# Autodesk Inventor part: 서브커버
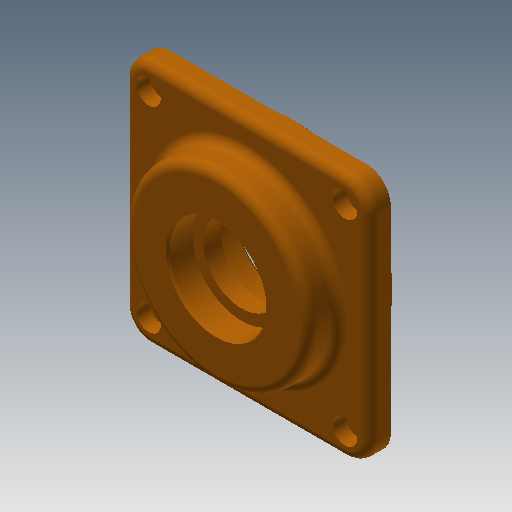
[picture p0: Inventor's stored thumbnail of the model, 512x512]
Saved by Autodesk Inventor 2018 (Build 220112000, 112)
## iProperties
Created: 2018-09
Part Number: 서브커버
Material: 알루미늄 6061
Document SubType Name: Modeling
Designer: mduedu
Density: 2.71 g/cm^3
Mass: 206.511 g
Surface Area: 197.007 cm^2
Volume: 76.2032 cm^3
Appearance: 주황색
Author: mduedu
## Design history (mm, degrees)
sketch "스케치1"
  geometry: L1 (-40, -40)-(40, -40); L2 (40, -40)-(40, 40); L3 (40, 40)-(-40, 40); L4 (-40, 40)-(-40, -40); L5 (-40, -40)-(40, 40); L6 (40, -40)-(-40, 40); 1 further point
  constraints: 12 end point, 2 midpoint, 2 parallel, 1 horizontal, 1 perpendicular
  dimensions: "d0" = 80 distance of L3.end L2.end; "d1" = 80 distance of L2.end L1.end
extrude "돌출1" new body sketch "스케치1" distance "d2" = 7; taper "d3" = 0 deg
sketch "스케치2"
  geometry: C1 r 30 at (0, 0); 1 further point
  constraints: 1 centre point, 1 coincident
  dimensions: "d4" = 60 diameter of C1
extrude "돌출2" join sketch "스케치2" distance "d5" = 10; taper "d6" = 0 deg
sketch "스케치3"
  geometry: C1 r 32.5 at (0, 0); 1 further point
  constraints: 1 centre point, 1 coincident
  dimensions: "d7" = 65 diameter of C1
extrude "돌출3" join sketch "스케치3" distance "d8" = 9; taper "d9" = 0 deg
sketch "스케치4"
  geometry: L1 (-32.5, -9)-(32.5, -9) reference; L2 (30, 17)-(-30, 17) reference; L3 (0, 17)-(0, -9); L4 (0, -9)-(20, -9); L5 (20, -9)-(20, 3); L6 (20, 3)-(0, 3); L7 (0, 3)-(0, -9); L8 (0, 3)-(12.5, 3); L9 (12.5, 3)-(12.5, 8.7); L10 (12.5, 8.7)-(0, 8.7); L11 (0, 8.7)-(0, 3); L12 (0, 8.7)-(16, 8.7); L13 (16, 8.7)-(16, 17); L14 (16, 17)-(0, 17); L15 (0, 17)-(0, 8.7); 1 further point
  constraints: 26 end point, 6 parallel, 3 horizontal, 3 perpendicular, 2 midpoint, 1 point on line
  dimensions: "d10" = 12 distance of L4.end L5.end; "d12" = 8.3 distance of L12.end L13.end; "d13" = 32 diameter of L13 L3; "d14" = 25 diameter of L9 L3; "d15" = 40 diameter of L5 L3
revolve "회전1" sketch "스케치4" stored, may be unused: angle "d16" = 90 deg
fillet "모깎기1" dims "d17" = 8
fillet "모깎기2" dims "d18" = 3
fillet "모깎기3" dims "d19" = 3
chamfer "모따기1" distance "d20" = 0.8; stored, may be unused: second distance "d21" = 2, angle "d22" = 30 deg
chamfer "모따기2" distance "d23" = 1; stored, may be unused: second distance "d24" = 2, angle "d25" = 30 deg
fillet "모깎기4" dims "d26" = 0.3
sketch "스케치5"
  geometry: A1 r 8 centre (-32, 32) between (-32, 40) and (-40, 32) reference; A2 r 8 centre (-32, -32) between (-40, -32) and (-32, -40) reference; A3 r 8 centre (32, -32) between (32, -40) and (40, -32) reference; A4 r 8 centre (32, 32) between (40, 32) and (32, 40) reference; 5 further points
  constraints: 4 coincident
hole "구멍1" sketch "스케치5" at (-32, 32), (32, 32), (32, -32), (-32, -32) diameter "d27" = 4.5; stored, may be unused: countersink angle "d31" = 90 deg, drill point angle "d33" = 118 deg; dims "d28" = 6, "d29" = 8, "d30" = 4.4, "d32" = 8
node "솔리드1"
